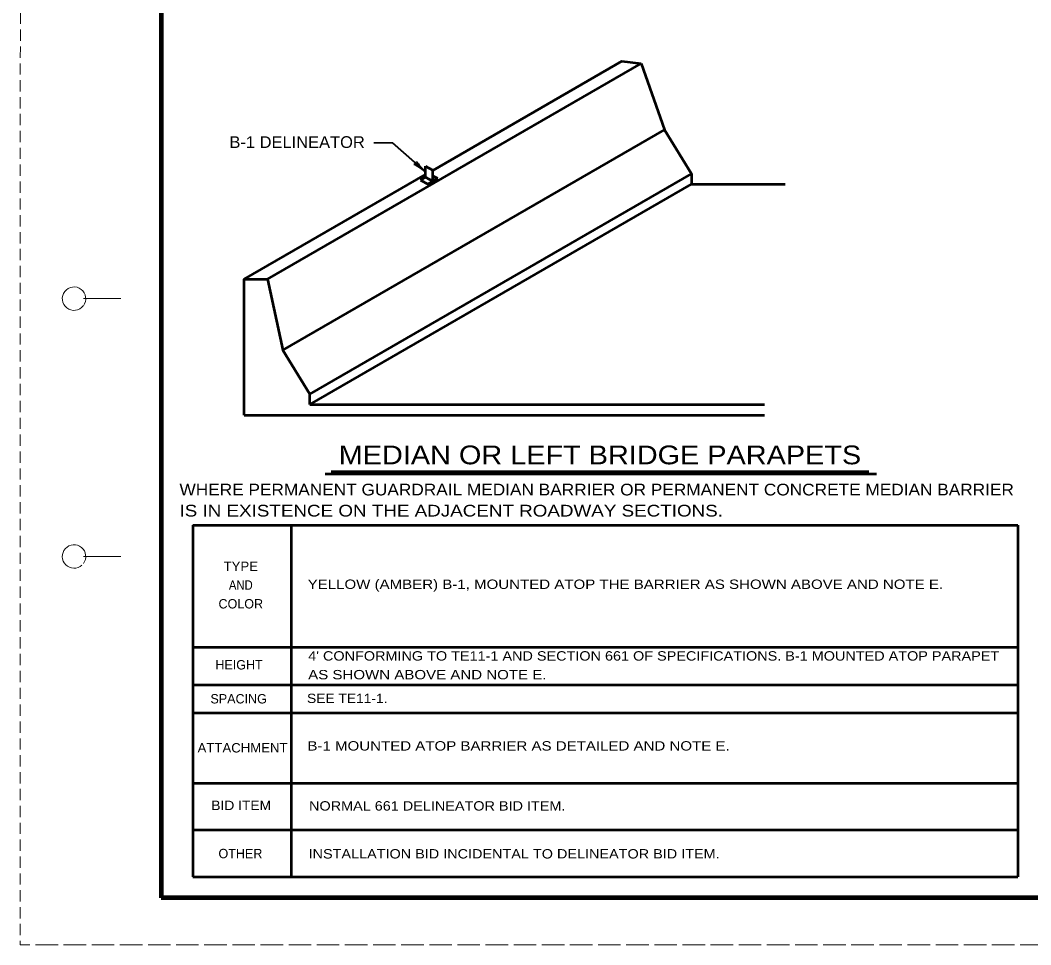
# Model space of a CAD drawing. Extents: x -60 to 620, y -42 to 398.
# Drawn here: x -60.3 to 155.3, y -41.8 to 155.5 of the extents above; entities that cross this region are included whole.
import ezdxf
from ezdxf.enums import TextEntityAlignment as Align

# ---------------------------------------------------------------- set-up
doc = ezdxf.new("R2010")
doc.units = 0
doc.header["$LTSCALE"] = 0.8
doc.linetypes.add('LONG_DASHED', pattern=[7.5, 6, -1.5])
doc.linetypes.add('MEDIUM_DASHED', pattern=[4.5, 3, -1.5])
doc.layers.add('1', color=7, linetype='Continuous', lineweight=35)
doc.layers.add('61', color=7, linetype='Continuous', lineweight=35)

msp = doc.modelspace()

# ---------------------------------------------------------------- linework, layer by layer
at = {"layer": '1', "linetype": 'MEDIUM_DASHED', "lineweight": 13}
msp.add_line((-60.2155, 398.2688), (-60.2755, -41.7713), dxfattribs=at)
at = {"layer": '1', "lineweight": 53}
for p, q in [((27.6961, 123.4382), (68.0239, 146.7215)), ((68.0239, 146.7215), (72.1579, 146.2215)), ((-7.5164, 100.2215), (72.1579, 146.2215)), ((-4.2938, 85.0602), (77.1127, 132.0602)), ((26.1336, 121.9679), (26.1336, 124.3117)), ((26.1336, 124.3117), (27.6961, 123.4707)), ((27.6961, 121.127), (27.6961, 123.4707)), ((-12.5164, 100.2215), (26.1336, 122.5361)), ((1.4836, 75.7215), (82.89, 122.7215)), ((25.1289, 121.3642), (26.1336, 121.9679)), ((25.1289, 121.3642), (26.7, 120.5092)), ((26.1336, 121.9679), (27.6961, 121.127)), ((26.6943, 120.5187), (27.6961, 121.127)), ((27.6906, 121.1363), (28.6923, 121.7447)), ((27.6961, 122.2868), (28.6923, 121.7447)), ((1.4836, 73.4715), (82.89, 120.4715)), ((1.4836, 73.4715), (1.4836, 75.7215)), ((1.4836, 73.4715), (98.4836, 73.4715)), ((-12.5164, 71.2215), (98.4836, 71.2215)), ((4.747, 58.6807), (122.3614, 58.6807)), ((6.0334, 59.1807), (120.7075, 59.1807)), ((-23.4869, 47.7191), (152.5131, 47.7191)), ((-23.4869, 47.7191), (-23.4869, -27.2809)), ((-2.4869, 47.7191), (-2.4869, -27.2809)), ((152.5131, 47.7191), (152.5131, -27.2809)), ((-23.4869, 21.7191), (152.5131, 21.7191)), ((-23.4869, 13.7191), (152.5131, 13.7191)), ((-23.4869, 7.7191), (152.5131, 7.7191)), ((-23.4869, -7.2809), (152.5131, -7.2809)), ((-23.4869, -17.2809), (152.5131, -17.2809)), ((-23.4869, -27.2809), (152.5131, -27.2809))]:
    msp.add_line(p, q, dxfattribs=at)
at = {"layer": '1'}
for p in [(15.112, 129.2845), (26.1336, 123.1398)]:
    msp.add_line(p, (19.1238, 129.2845), dxfattribs=at)
at = {"layer": '1', "lineweight": 53}
for points in [[(72.1579, 146.2215), (77.1127, 132.0602), (82.89, 122.7215), (82.89, 120.4715), (102.89, 120.4715)], [(-12.5164, 71.2215), (-12.5164, 100.2215), (-7.5164, 100.2215)], [(-7.5164, 100.2215), (-4.2938, 85.0602), (1.4836, 75.7215)]]:
    msp.add_lwpolyline(points, dxfattribs=at)
at = {"layer": '1', "lineweight": 40}
for centre, major_axis, ratio, start_param, end_param in [((25.4305, 124.0376), (1.205, -1.2899), 0.07063, 3.14071475, 5.41810995), ((25.1309, 123.6514), (1.4458, -1.0597), 0.122415, 0.89635335, 3.14159265)]:
    msp.add_ellipse(centre, major_axis=major_axis, ratio=ratio, start_param=start_param, end_param=end_param, dxfattribs=at)
at = {"layer": '61', "lineweight": 13}
for p, q in [((-46.7955, 96.0887), (-38.7955, 96.0887)), ((-46.7755, 41.0688), (-38.7955, 41.0688))]:
    msp.add_line(p, q, dxfattribs=at)
at = {"layer": '61', "lineweight": 158}
msp.add_line((608.8445, -31.7712), (-30.2155, -31.7512), dxfattribs=at)
at = {"layer": '61', "linetype": 'LONG_DASHED', "lineweight": 13}
msp.add_line((619.7845, -41.7512), (-60.2755, -41.7713), dxfattribs=at)
at = {"layer": '61', "lineweight": 158}
msp.add_lwpolyline([(608.8245, 388.2688), (-30.2155, 388.2688), (-30.2155, -31.7512)], dxfattribs=at)
at = {"layer": '61', "lineweight": 13}
for centre, start, end in [((-48.7977, 96.07), 322.67175, 321.71615), ((-48.7977, 41.07), 323.13009, 312.31439)]:
    msp.add_arc(centre, 2.5, start, end, dxfattribs=at)

# ---------------------------------------------------------------- texts
at = {"layer": '1'}
for s, height, width, p in [('B-1 DELINEATOR', 2.5, 1.05, (-15.6492, 128.215)), ('MEDIAN OR LEFT BRIDGE PARAPETS', 4, 1.15, (7.6637, 60.7328)), ('WHERE PERMANENT GUARDRAIL MEDIAN BARRIER OR PERMANENT CONCRETE MEDIAN BARRIER', 2.5, 1.1, (-26.3022, 54.09)), ('IS IN EXISTENCE ON THE ADJACENT ROADWAY SECTIONS.', 2.5, 1.2, (-26.3022, 49.59)), ('YELLOW (AMBER) B-1, MOUNTED ATOP THE BARRIER AS SHOWN ABOVE AND NOTE E.', 2, 1.2, (1.0343, 34.1461)), ("4' CONFORMING TO TE11-1 AND SECTION 661 OF SPECIFICATIONS. B-1 MOUNTED ATOP PARAPET", 2, 1.15, (1.146, 18.8569)), ('AS SHOWN ABOVE AND NOTE E.', 2, 1.2, (1.146, 14.8569)), ('B-1 MOUNTED ATOP BARRIER AS DETAILED AND NOTE E.', 2, 1.2, (0.9857, -0.3356))]:
    msp.add_text(s, height=height, dxfattribs=dict(at, width=width)).set_placement(p)
for s, width, p in [('TYPE', 1.05, (-13.2268, 37.9751)), ('AND', 0.9, (-13.2268, 33.9751)), ('SEE TE11-1.', 1.1, (9.4828, 9.8008)), ('ATTACHMENT', 1.05, (-12.8501, -0.7461)), ('BID ITEM', 1.1, (-13.1448, -13.0296)), ('NORMAL 661 DELINEATOR BID ITEM.', 1.15, (28.6711, -13.1385)), ('INSTALLATION BID INCIDENTAL TO DELINEATOR BID ITEM.', 1.15, (45.0637, -23.3619))]:
    msp.add_text(s, height=2, dxfattribs=dict(at, width=width)).set_placement(p, align=Align.CENTER)
for s, p in [('COLOR', (-13.2269, 29.9751)), ('HEIGHT', (-13.6032, 16.9572)), ('SPACING', (-13.6852, 9.7108)), ('OTHER', (-13.3087, -23.3061))]:
    msp.add_text(s, height=2, dxfattribs=at).set_placement(p, align=Align.CENTER)

doc.saveas('drawing.dxf')
